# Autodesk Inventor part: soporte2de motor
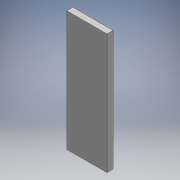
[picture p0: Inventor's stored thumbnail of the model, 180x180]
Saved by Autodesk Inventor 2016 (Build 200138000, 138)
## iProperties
Created: 2016-06
Part Number: soporte2de motor
Material: Genérico
Document SubType Name: Modeling
Designer: adm
Density: 1 g/cm^3
Appearance: Valor por defecto
Author: adm
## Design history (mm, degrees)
sketch "Boceto1"
  geometry: L1 (-10, -1.5)-(10, -1.5); L2 (10, -1.5)-(10, 1.5); L3 (10, 1.5)-(-10, 1.5); L4 (-10, 1.5)-(-10, -1.5); L5 (-10, -1.5)-(10, 1.5); L6 (10, -1.5)-(-10, 1.5); 1 further point
  constraints: 12 end point, 2 midpoint, 2 parallel, 1 horizontal, 1 perpendicular
  dimensions: "d0" = 20 distance of L3.end L2.end; "d1" = 3 distance of L2.end L1.end
extrude "Extrusión1" new body sketch "Boceto1" distance "d2" = 60; taper "d3" = 0 deg
node "Sólido1"
